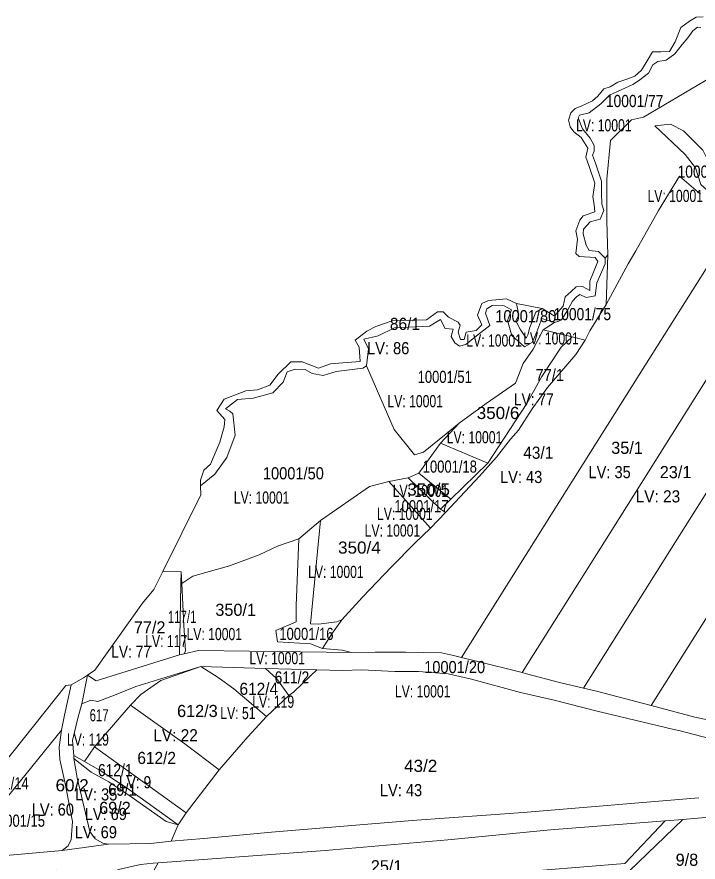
# Model space of a CAD drawing. Extents: x -713758 to -711119, y -1123067 to -1120789.
# Drawn here: x -712790 to -712228, y -1121659 to -1120963 of the extents above; entities that cross this region are included whole.
import ezdxf
from ezdxf.enums import TextEntityAlignment as Align

# ---------------------------------------------------------------- set-up
doc = ezdxf.new("R2010")
doc.units = 0
doc.header["$LTSCALE"] = 4
doc.layers.add('10', color=7, linetype='Continuous', lineweight=13)
doc.layers.add('11', color=7, linetype='Continuous')
doc.layers.add('13', color=7, linetype='Continuous')

msp = doc.modelspace()

# ---------------------------------------------------------------- linework, layer by layer
at = {"layer": '10'}
for points in [[(-712224.42, -1120963.08), (-712229.97, -1120963.16), (-712235.67, -1120966.55), (-712242.84, -1120971.92), (-712247.51, -1120983.72), (-712252.15, -1120991.62), (-712259.23, -1120991.94), (-712265.98, -1120991.96), (-712269.53, -1120998.02), (-712275.11, -1121006.86), (-712280.51, -1121011.9), (-712287.26, -1121014.28), (-712294.69, -1121016.71), (-712301.06, -1121020.69), (-712306.12, -1121022.38), (-712311.08, -1121028.3), (-712315.59, -1121032.08), (-712324.92, -1121036.66), (-712329.84, -1121038.62), (-712333.26, -1121042), (-712335.14, -1121048.22), (-712333.91, -1121053.74), (-712330.79, -1121057.62), (-712324.87, -1121062.34), (-712319.39, -1121071.27), (-712320.86, -1121078.69), (-712318.44, -1121085.37), (-712313.44, -1121100.01), (-712315.07, -1121111.24), (-712314.22, -1121117.5), (-712313.51, -1121123.67), (-712323.15, -1121126.92), (-712326.04, -1121130.58), (-712329.29, -1121139.33), (-712327.88, -1121146.11), (-712329.21, -1121158.1), (-712326.58, -1121160.43), (-712313.32, -1121161.17), (-712311.05, -1121164.48), (-712317.66, -1121180.78), (-712317.8, -1121188.36), (-712323.7, -1121185.03), (-712328.84, -1121185.35), (-712333.17, -1121189.3), (-712338.01, -1121193.72), (-712339.74, -1121201.43), (-712345.99, -1121208.39), (-712347.16, -1121209.3), (-712356.85, -1121203.31), (-712362.25, -1121206.21), (-712367.35, -1121219.37), (-712368.35, -1121224.5), (-712370.05, -1121227.81), (-712374.93, -1121220.33), (-712378.6, -1121213.35), (-712376.17, -1121208.67), (-712377.96, -1121199.21), (-712386.36, -1121195.27), (-712401.25, -1121196.63), (-712406.58, -1121199.11), (-712410.2, -1121208.83), (-712406.61, -1121216.8), (-712411.25, -1121221.32), (-712419.44, -1121222.82), (-712421.3, -1121228.7), (-712424.22, -1121228.79), (-712426.03, -1121222.66), (-712424.52, -1121217.12), (-712426.11, -1121214.63), (-712433.99, -1121210.38), (-712438.39, -1121206.13), (-712443.23, -1121206), (-712452.25, -1121212.71), (-712480.57, -1121213.53), (-712493.91, -1121218.11), (-712501.44, -1121222), (-712510.87, -1121229.48), (-712507.74, -1121235.25), (-712506.94, -1121246.96), (-712521.16, -1121247.99), (-712531.15, -1121248.85), (-712541.21, -1121252.33), (-712554.73, -1121247.31), (-712563.93, -1121247.29), (-712574.37, -1121257.45), (-712581.16, -1121266.47), (-712591.37, -1121270.33), (-712601.07, -1121271.03), (-712618.97, -1121277.89), (-712624.92, -1121287.25), (-712618.24, -1121294.85), (-712618.97, -1121300.73), (-712622.46, -1121313.42), (-712630.21, -1121331.54), (-712635.65, -1121336.52), (-712638.35, -1121344.65)], [(-712638.35, -1121344.65), (-712638.25, -1121349.38), (-712626.66, -1121339.88), (-712616.75, -1121326.09), (-712609.88, -1121307.54), (-712611.65, -1121290.13), (-712614.07, -1121287.84), (-712617.67, -1121285.95), (-712608.01, -1121278.11), (-712595.1, -1121277.06), (-712578.88, -1121272.62), (-712570.35, -1121263.93), (-712566.99, -1121255.5), (-712560.35, -1121253.18), (-712552.18, -1121253.58), (-712546.45, -1121256.89), (-712537.32, -1121258.45), (-712526.61, -1121255.29), (-712504.52, -1121252.44), (-712501.54, -1121250.48), (-712499.95, -1121236.38), (-712503.89, -1121228.47), (-712492.06, -1121225.81), (-712478.69, -1121219.22), (-712449.86, -1121217.79), (-712440.6, -1121212.38), (-712436.8, -1121219.7), (-712430.19, -1121220.2), (-712431.89, -1121226.25), (-712428.83, -1121231.53), (-712425.14, -1121234.31), (-712419.72, -1121232.98), (-712411.12, -1121225.79), (-712400.13, -1121217.31), (-712403.66, -1121207.21), (-712402.46, -1121203.44), (-712398.09, -1121200.87), (-712388.2, -1121200.98), (-712382.24, -1121204.31), (-712385.36, -1121213.25), (-712383.29, -1121220.86), (-712381.98, -1121225.65), (-712371.56, -1121234.82), (-712365.19, -1121231.4), (-712361.26, -1121222.53), (-712357.3, -1121211.49), (-712346.86, -1121214.84), (-712343.33, -1121213.8), (-712341.01, -1121212.69), (-712335.87, -1121204.25), (-712332.04, -1121197.29), (-712328.59, -1121193.6), (-712325.78, -1121191.79), (-712320.65, -1121194.25), (-712313.38, -1121192.75), (-712312, -1121182.24), (-712305.08, -1121166.47), (-712304.91, -1121161.72), (-712310.51, -1121156.25), (-712318.21, -1121155.46), (-712320.69, -1121151.04), (-712323.08, -1121141.82), (-712322.96, -1121137.97), (-712317.36, -1121131.81), (-712309.25, -1121129.8), (-712306.17, -1121122.47), (-712307.76, -1121117.45), (-712308.2, -1121108.1), (-712307.98, -1121098.34), (-712313.12, -1121083.51), (-712315.41, -1121077.09), (-712314, -1121073.54), (-712314.06, -1121069.02), (-712317.38, -1121063.06), (-712323.6, -1121055.16), (-712327.17, -1121046.2), (-712326.21, -1121044.06), (-712318.11, -1121042.2), (-712308.59, -1121034.55), (-712301.53, -1121027.44), (-712282.23, -1121018.77), (-712277.62, -1121015.73), (-712269.32, -1121009.56), (-712265.82, -1121002.65), (-712261.78, -1120999.7), (-712254.92, -1120998.58), (-712247.54, -1120993.58), (-712241.71, -1120985.84), (-712236.9, -1120980.4), (-712232.78, -1120974.54), (-712229.02, -1120971.51), (-712226.11, -1120971.88)], [(-712226.11, -1120971.88), (-712229.02, -1120971.51), (-712232.78, -1120974.54), (-712236.9, -1120980.4), (-712241.71, -1120985.84), (-712247.54, -1120993.58), (-712254.92, -1120998.58), (-712261.78, -1120999.7), (-712265.82, -1121002.65), (-712269.32, -1121009.56), (-712277.62, -1121015.73), (-712282.23, -1121018.77), (-712301.53, -1121027.44), (-712308.59, -1121034.55), (-712318.11, -1121042.2), (-712326.21, -1121044.06), (-712327.17, -1121046.2), (-712323.6, -1121055.16), (-712317.38, -1121063.06), (-712314.06, -1121069.02), (-712314, -1121073.54), (-712315.41, -1121077.09), (-712313.12, -1121083.51), (-712307.98, -1121098.34), (-712308.2, -1121108.1), (-712307.76, -1121117.45), (-712306.17, -1121122.47), (-712309.25, -1121129.8), (-712317.36, -1121131.81), (-712322.96, -1121137.97), (-712323.08, -1121141.82), (-712320.69, -1121151.04), (-712318.21, -1121155.46), (-712310.51, -1121156.25), (-712304.91, -1121161.72), (-712302.77, -1121158.96), (-712303.66, -1121131.47), (-712303.73, -1121096.86), (-712300.52, -1121064.83), (-712283.37, -1121047.99), (-712273.5, -1121045.77), (-712206.41, -1121006.04)], [(-712206.41, -1121006.04), (-712273.5, -1121045.77), (-712283.37, -1121047.99), (-712300.52, -1121064.83), (-712303.73, -1121096.86), (-712303.66, -1121131.47), (-712302.77, -1121158.96), (-712304.25, -1121199.91), (-712286.23, -1121166.59), (-712279.75, -1121155.73), (-712261.06, -1121122.55), (-712243.93, -1121094.31), (-712226.54, -1121109.19)], [(-712226.54, -1121109.19), (-712243.93, -1121094.31), (-712261.06, -1121122.55), (-712279.75, -1121155.73), (-712286.23, -1121166.59), (-712304.25, -1121199.91), (-712317.68, -1121221.61), (-712321.65, -1121229.23), (-712329.15, -1121241.06), (-712352.43, -1121268.46), (-712365.29, -1121286.03), (-712376.38, -1121303.44), (-712383, -1121310.86), (-712394.56, -1121325.76), (-712408.42, -1121341.27), (-712436.67, -1121371.26), (-712448.79, -1121384.35), (-712461.76, -1121396.57), (-712480.93, -1121416.03), (-712504.85, -1121441.12), (-712521.96, -1121459.65), (-712530.11, -1121471.27), (-712537.77, -1121483.27), (-712521.76, -1121484.83), (-712514.05, -1121486.77), (-712494.46, -1121486.25), (-712469.39, -1121486.31), (-712439.94, -1121487.05), (-712430.1, -1121488.99), (-712423.44, -1121490.64), (-712347.85, -1121370.61), (-712272.26, -1121250.57), (-712196.67, -1121130.54)], [(-712221.92, -1121541.87), (-712231.21, -1121539.78), (-712267.18, -1121530.34), (-712312.23, -1121518.51), (-712322.84, -1121515.97), (-712342.53, -1121511.25), (-712369.84, -1121504.13), (-712373.44, -1121503.22), (-712411.12, -1121493.7), (-712423.44, -1121490.64), (-712430.1, -1121488.99), (-712439.94, -1121487.05), (-712469.39, -1121486.31), (-712494.46, -1121486.25), (-712514.05, -1121486.77), (-712639.91, -1121484.94), (-712651.92, -1121487.77), (-712655.74, -1121488.57), (-712724.24, -1121509.87), (-712731.39, -1121505.21), (-712736.15, -1121529.01), (-712728.69, -1121525.95), (-712722.98, -1121527.12), (-712709.28, -1121521.78), (-712691.5, -1121514.66), (-712638.03, -1121498.16), (-712584.9, -1121499.71), (-712542.46, -1121500.8), (-712521.21, -1121501.35), (-712505.59, -1121500.85), (-712478.34, -1121502.43), (-712458.67, -1121502.22), (-712434.5, -1121504.3), (-712415.23, -1121508.73), (-712374.86, -1121519.68), (-712347.09, -1121525.83), (-712311.55, -1121535.01), (-712249.63, -1121549.72), (-712243.26, -1121551.08), (-712212.92, -1121559.2)], [(-712212.92, -1121559.2), (-712243.26, -1121551.08), (-712249.63, -1121549.72), (-712311.55, -1121535.01), (-712347.09, -1121525.83), (-712374.86, -1121519.68), (-712415.23, -1121508.73), (-712434.5, -1121504.3), (-712458.67, -1121502.22), (-712478.34, -1121502.43), (-712505.59, -1121500.85), (-712521.21, -1121501.35), (-712542.46, -1121500.8), (-712547.82, -1121505.92), (-712561.9, -1121519.34), (-712565.66, -1121522.02), (-712584.01, -1121539.3), (-712599.25, -1121556.05), (-712623, -1121583.43), (-712650.07, -1121618.72), (-712656.83, -1121628.57), (-712662.45, -1121642.03), (-712635.72, -1121639.83), (-712580.02, -1121634.77), (-712464.09, -1121624.94), (-712372.57, -1121618.47), (-712228.02, -1121606.32)], [(-712829.35, -1121656.74), (-712752.3, -1121649.86), (-712714.25, -1121644.62), (-712679.19, -1121643.9), (-712662.45, -1121642.03), (-712635.72, -1121639.83), (-712580.02, -1121634.77), (-712464.09, -1121624.94), (-712372.57, -1121618.47), (-712228.02, -1121606.32)], [(-712201.33, -1121620.73), (-712241.17, -1121624.1), (-712255.74, -1121625.24), (-712350.1, -1121632.59), (-712434.68, -1121640.83), (-712535.55, -1121649.68), (-712673.12, -1121659.8), (-712677.41, -1121660.12), (-712687.79, -1121661.3), (-712705.83, -1121665.37), (-712711.27, -1121667.93), (-712716.34, -1121673.15), (-712734.88, -1121675.75), (-712740.68, -1121669.42), (-712748.52, -1121666.41), (-712756.64, -1121665.93), (-712811.56, -1121670.57)], [(-712284.89, -1121666.46), (-712241.17, -1121624.1), (-712255.74, -1121625.24), (-712288.77, -1121660.36)]]:
    msp.add_lwpolyline(points, dxfattribs=at)
for points in [[(-712264.11, -1121052.71), (-712239.09, -1121076.45), (-712230.76, -1121087.53), (-712226.25, -1121101.15), (-712200.43, -1121124.56), (-712186.09, -1121132.32), (-712178.22, -1121136.29), (-712166.82, -1121136.13), (-712166.03, -1121127.39), (-712177.11, -1121119.56), (-712186.97, -1121112.79), (-712203.92, -1121102.45), (-712218.34, -1121085.52), (-712224.47, -1121072.79), (-712240.53, -1121057.06), (-712251.27, -1121051.42)], [(-712264.11, -1121052.71), (-712251.27, -1121051.42), (-712240.53, -1121057.06), (-712224.47, -1121072.79), (-712218.34, -1121085.52), (-712203.92, -1121102.45), (-712186.97, -1121112.79), (-712177.11, -1121119.56), (-712166.03, -1121127.39), (-712166.82, -1121136.13), (-712178.22, -1121136.29), (-712186.09, -1121132.32), (-712200.43, -1121124.56), (-712226.25, -1121101.15), (-712230.76, -1121087.53), (-712239.09, -1121076.45)], [(-712423.44, -1121490.64), (-712347.85, -1121370.61), (-712272.26, -1121250.57), (-712196.67, -1121130.54), (-712185, -1121136.71), (-712169.32, -1121143.39), (-712151.71, -1121151.12), (-712225.62, -1121268.49), (-712299.53, -1121385.85), (-712373.44, -1121503.22), (-712411.12, -1121493.7)], [(-712373.44, -1121503.22), (-712299.53, -1121385.85), (-712225.62, -1121268.49), (-712151.71, -1121151.12), (-712121.32, -1121164.46), (-712105.15, -1121170.27), (-712177.71, -1121285.5), (-712250.27, -1121400.74), (-712322.84, -1121515.97), (-712342.53, -1121511.25), (-712369.84, -1121504.13)], [(-712356.08, -1121220.95), (-712332.16, -1121226.7), (-712321.65, -1121229.23), (-712317.68, -1121221.61), (-712304.25, -1121199.91), (-712302.77, -1121158.96), (-712304.91, -1121161.72), (-712305.08, -1121166.47), (-712312, -1121182.24), (-712313.38, -1121192.75), (-712320.65, -1121194.25), (-712325.78, -1121191.79), (-712328.59, -1121193.6), (-712332.04, -1121197.29), (-712335.87, -1121204.25), (-712341.01, -1121212.69), (-712343.33, -1121213.8), (-712346.86, -1121214.84)], [(-712322.84, -1121515.97), (-712250.27, -1121400.74), (-712177.71, -1121285.5), (-712105.15, -1121170.27), (-712076.52, -1121180.56), (-712064.5, -1121183.42), (-712050.6, -1121186.42), (-712122.79, -1121301.06), (-712194.99, -1121415.7), (-712267.18, -1121530.34), (-712312.23, -1121518.51)], [(-712267.18, -1121530.34), (-712194.99, -1121415.7), (-712122.79, -1121301.06), (-712050.6, -1121186.42), (-712045.54, -1121187.51), (-712026.93, -1121189.41), (-712000.06, -1121191.51), (-712073.66, -1121308.39), (-712147.26, -1121425.26), (-712220.86, -1121542.14), (-712221.92, -1121541.87), (-712231.21, -1121539.78)], [(-712503.89, -1121228.47), (-712499.95, -1121236.38), (-712501.54, -1121250.48), (-712478.94, -1121303.07), (-712462.23, -1121323.77), (-712454.65, -1121321.49), (-712436.07, -1121306.41), (-712425.21, -1121297.67), (-712403.14, -1121281.61), (-712378.77, -1121264.75), (-712372.68, -1121248.63), (-712364.35, -1121236.66), (-712356.08, -1121220.95), (-712346.86, -1121214.84), (-712357.3, -1121211.49), (-712361.26, -1121222.53), (-712365.19, -1121231.4), (-712371.56, -1121234.82), (-712381.98, -1121225.65), (-712383.29, -1121220.86), (-712385.36, -1121213.25), (-712382.24, -1121204.31), (-712388.2, -1121200.98), (-712398.09, -1121200.87), (-712402.46, -1121203.44), (-712403.66, -1121207.21), (-712400.13, -1121217.31), (-712411.12, -1121225.79), (-712419.72, -1121232.98), (-712425.14, -1121234.31), (-712428.83, -1121231.53), (-712431.89, -1121226.25), (-712430.19, -1121220.2), (-712436.8, -1121219.7), (-712440.6, -1121212.38), (-712449.86, -1121217.79), (-712478.69, -1121219.22), (-712492.06, -1121225.81)], [(-712378.6, -1121213.35), (-712374.93, -1121220.33), (-712370.05, -1121227.81), (-712368.35, -1121224.5), (-712367.35, -1121219.37), (-712362.25, -1121206.21), (-712356.85, -1121203.31), (-712377.96, -1121199.21), (-712376.17, -1121208.67)], [(-712440.65, -1121314.3), (-712401.72, -1121330.62), (-712369.68, -1121281.6), (-712357.24, -1121259.22), (-712341.2, -1121235.2), (-712332.16, -1121226.7), (-712356.08, -1121220.95), (-712364.35, -1121236.66), (-712372.68, -1121248.63), (-712378.77, -1121264.75), (-712403.14, -1121281.61), (-712425.21, -1121297.67)], [(-712440.61, -1121368.69), (-712436.67, -1121371.26), (-712408.42, -1121341.27), (-712394.56, -1121325.76), (-712383, -1121310.86), (-712376.38, -1121303.44), (-712365.29, -1121286.03), (-712352.43, -1121268.46), (-712329.15, -1121241.06), (-712321.65, -1121229.23), (-712332.16, -1121226.7), (-712341.2, -1121235.2), (-712357.24, -1121259.22), (-712369.68, -1121281.6), (-712401.72, -1121330.62), (-712432.15, -1121360.41)], [(-712669.26, -1121419.84), (-712654.24, -1121420.15), (-712653.78, -1121429.78), (-712644.81, -1121423.71), (-712614.56, -1121415.28), (-712589.95, -1121406.22), (-712575.05, -1121398.94), (-712557.36, -1121393), (-712539.39, -1121377.79), (-712499.03, -1121349.77), (-712483.18, -1121345.84), (-712467.38, -1121342.75), (-712458.58, -1121338.81), (-712440.65, -1121314.3), (-712425.21, -1121297.67), (-712436.07, -1121306.41), (-712454.65, -1121321.49), (-712462.23, -1121323.77), (-712478.94, -1121303.07), (-712501.54, -1121250.48), (-712504.52, -1121252.44), (-712526.61, -1121255.29), (-712537.32, -1121258.45), (-712546.45, -1121256.89), (-712552.18, -1121253.58), (-712560.35, -1121253.18), (-712566.99, -1121255.5), (-712570.35, -1121263.93), (-712578.88, -1121272.62), (-712595.1, -1121277.06), (-712608.01, -1121278.11), (-712617.67, -1121285.95), (-712614.07, -1121287.84), (-712611.65, -1121290.13), (-712609.88, -1121307.54), (-712616.75, -1121326.09), (-712626.66, -1121339.88), (-712638.25, -1121349.38), (-712638.1, -1121356.72)], [(-712458.58, -1121338.81), (-712432.15, -1121360.41), (-712401.72, -1121330.62), (-712440.65, -1121314.3)], [(-712483.18, -1121345.84), (-712448.79, -1121384.35), (-712436.67, -1121371.26), (-712440.61, -1121368.69), (-712467.38, -1121342.75)], [(-712467.38, -1121342.75), (-712440.61, -1121368.69), (-712432.15, -1121360.41), (-712458.58, -1121338.81)], [(-712547.79, -1121463.01), (-712541.23, -1121463.22), (-712526.04, -1121461.35), (-712521.96, -1121459.65), (-712504.85, -1121441.12), (-712480.93, -1121416.03), (-712461.76, -1121396.57), (-712448.79, -1121384.35), (-712483.18, -1121345.84), (-712499.03, -1121349.77), (-712539.39, -1121377.79)], [(-712576.37, -1121468.4), (-712575.02, -1121477.85), (-712547.66, -1121479.54), (-712537.77, -1121483.27), (-712530.11, -1121471.27), (-712521.96, -1121459.65), (-712526.04, -1121461.35), (-712541.23, -1121463.22), (-712547.79, -1121463.01), (-712539.39, -1121377.79), (-712557.36, -1121393), (-712559.64, -1121447.91), (-712559.68, -1121461.33)], [(-712653.78, -1121429.78), (-712652.12, -1121464.34), (-712650.65, -1121485.2), (-712651.92, -1121487.77), (-712639.91, -1121484.94), (-712514.05, -1121486.77), (-712521.76, -1121484.83), (-712537.77, -1121483.27), (-712547.66, -1121479.54), (-712575.02, -1121477.85), (-712576.37, -1121468.4), (-712559.68, -1121461.33), (-712559.64, -1121447.91), (-712557.36, -1121393), (-712575.05, -1121398.94), (-712589.95, -1121406.22), (-712614.56, -1121415.28), (-712644.81, -1121423.71)], [(-712731.39, -1121505.21), (-712724.24, -1121509.87), (-712655.74, -1121488.57), (-712654.48, -1121430.25), (-712654.24, -1121420.15), (-712669.26, -1121419.84), (-712676.89, -1121434.62), (-712686.18, -1121445.9), (-712725.31, -1121501.17)], [(-712655.74, -1121488.57), (-712654.48, -1121430.25), (-712654.24, -1121420.15), (-712653.78, -1121429.78), (-712652.12, -1121464.34), (-712650.65, -1121485.2), (-712651.92, -1121487.77)], [(-712743.86, -1121559.24), (-712742.8, -1121571.5), (-712734.01, -1121576.43), (-712725.74, -1121564.24), (-712696.07, -1121529.89), (-712687.53, -1121521.3), (-712671.17, -1121509.65), (-712638.03, -1121498.16), (-712691.5, -1121514.66), (-712709.28, -1121521.78), (-712722.98, -1121527.12), (-712728.69, -1121525.95), (-712736.15, -1121529.01), (-712739.03, -1121539.72)], [(-712696.07, -1121529.89), (-712651.29, -1121561.99), (-712623, -1121583.43), (-712599.25, -1121556.05), (-712584.01, -1121539.3), (-712610.8, -1121516.6), (-712623.7, -1121507.1), (-712638.03, -1121498.16), (-712671.17, -1121509.65), (-712687.53, -1121521.3)], [(-712638.03, -1121498.16), (-712623.7, -1121507.1), (-712610.8, -1121516.6), (-712584.01, -1121539.3), (-712565.66, -1121522.02), (-712575.68, -1121507.96), (-712584.9, -1121499.71)], [(-712584.9, -1121499.71), (-712542.46, -1121500.8), (-712547.82, -1121505.92), (-712561.9, -1121519.34), (-712565.66, -1121522.02), (-712575.68, -1121507.96)], [(-712754.67, -1121564.53), (-712754.14, -1121574.84), (-712749.88, -1121594.58), (-712743.67, -1121625.84), (-712745.02, -1121640.69), (-712747.43, -1121645.94), (-712752.3, -1121649.86), (-712714.25, -1121644.62), (-712718.91, -1121643.72), (-712725.1, -1121640.01), (-712729.48, -1121634.07), (-712739.94, -1121589.8), (-712742.6, -1121573.83), (-712742.8, -1121571.5), (-712743.86, -1121559.24), (-712739.03, -1121539.72), (-712736.15, -1121529.01), (-712731.39, -1121505.21), (-712734.73, -1121507.43), (-712744.77, -1121513.2), (-712750.3, -1121538.21), (-712752.88, -1121550.69)], [(-712888.87, -1121658.79), (-712885.65, -1121658.68), (-712864.22, -1121657.94), (-712845.67, -1121640.48), (-712817.6, -1121624.66), (-712795.86, -1121603.97), (-712752.88, -1121550.69), (-712750.3, -1121538.21), (-712744.77, -1121513.2), (-712749.34, -1121513.8), (-712811.48, -1121591.48), (-712818.41, -1121597.09), (-712831.79, -1121610.57), (-712848.31, -1121615.15), (-712856.5, -1121624.23), (-712868.15, -1121630.5), (-712882.05, -1121646.55)], [(-712725.74, -1121564.24), (-712650.07, -1121618.72), (-712623, -1121583.43), (-712651.29, -1121561.99), (-712696.07, -1121529.89)], [(-712864.22, -1121657.94), (-712829.35, -1121656.74), (-712752.3, -1121649.86), (-712747.43, -1121645.94), (-712745.02, -1121640.69), (-712743.67, -1121625.84), (-712749.88, -1121594.58), (-712754.14, -1121574.84), (-712754.67, -1121564.53), (-712752.88, -1121550.69), (-712795.86, -1121603.97), (-712817.6, -1121624.66), (-712845.67, -1121640.48)], [(-712734.01, -1121576.43), (-712721.13, -1121583.73), (-712698.68, -1121598.5), (-712656.83, -1121628.57), (-712650.07, -1121618.72), (-712725.74, -1121564.24)], [(-712742.8, -1121571.5), (-712742.6, -1121573.83), (-712728.48, -1121585.2), (-712713.98, -1121593.15), (-712695.58, -1121605.66), (-712666.53, -1121625.95), (-712656.83, -1121628.57), (-712698.68, -1121598.5), (-712721.13, -1121583.73), (-712734.01, -1121576.43)], [(-712742.6, -1121573.83), (-712739.94, -1121589.8), (-712729.48, -1121634.07), (-712725.1, -1121640.01), (-712718.91, -1121643.72), (-712714.25, -1121644.62), (-712679.19, -1121643.9), (-712662.45, -1121642.03), (-712656.83, -1121628.57), (-712666.53, -1121625.95), (-712695.58, -1121605.66), (-712713.98, -1121593.15), (-712728.48, -1121585.2)], [(-712310.25, -1121694.64), (-712229.88, -1121697.85), (-712138.38, -1121614.8), (-712201.33, -1121620.73), (-712241.17, -1121624.1), (-712284.89, -1121666.46)], [(-712693.92, -1121693.86), (-712685.27, -1121681.19), (-712673.12, -1121659.8), (-712535.55, -1121649.68), (-712434.68, -1121640.83), (-712350.1, -1121632.59), (-712255.74, -1121625.24), (-712288.77, -1121660.36), (-712423.82, -1121671.53), (-712558.87, -1121682.69)]]:
    msp.add_lwpolyline(points, close=True, dxfattribs=at)

# ---------------------------------------------------------------- texts
at = {"layer": '11'}
for s, width, p in [('10001/77', 0.85, (-712280.73, -1121037.36)), ('10001/76', 0.85, (-712221.69, -1121095.54)), ('10001/80', 0.9, (-712370.441, -1121214.61)), ('10001/75', 0.85, (-712323.851, -1121212.9)), ('86/1', 0.95, (-712469.99, -1121220.96)), ('10001/51', 0.8, (-712437.2, -1121264.6)), ('77/1', 0.9, (-712350.67, -1121263.12)), ('350/6', 1.05, (-712393.299, -1121294.33)), ('43/1', 0.95, (-712360.15, -1121327.06)), ('10001/18', 0.8, (-712433, -1121338.51)), ('10001/50', 0.9, (-712561.87, -1121344.02)), ('350/5', 1.05, (-712450.5, -1121357.39)), ('10001/17', 0.8, (-712456.38, -1121371.15)), ('350/4', 1.05, (-712507.48, -1121405.22)), ('117/1', 0.7, (-712653.46, -1121462.24)), ('10001/16', 0.8, (-712551.111, -1121476.28)), ('10001/20', 0.9, (-712429.03, -1121503.64)), ('611/2', 0.85, (-712563.061, -1121512.16)), ('612/4', 0.95, (-712590.351, -1121521.54)), ('617', 0.7, (-712721.89, -1121543.33)), ('612/2', 0.95, (-712674.481, -1121578.51)), ('43/2', 1.05, (-712456.99, -1121585.02)), ('612/1', 0.85, (-712708.561, -1121588.52)), ('10001/14', 0.8, (-712802.16, -1121599.44)), ('60/2', 1.05, (-712744.1, -1121601)), ('69/1', 0.9, (-712702.73, -1121604.64)), ('10001/15', 0.8, (-712788.78, -1121630.19))]:
    msp.add_text(s, height=10, dxfattribs=dict(at, width=width)).set_placement(p, align=Align.CENTER)
for s, p in [('35/1', (-712287.049, -1121323.04)), ('23/1', (-712247.059, -1121343.03)), ('350/1', (-712609.4, -1121456.45)), ('77/2', (-712680.25, -1121470.95)), ('612/3', (-712640.929, -1121539.8)), ('69/2', (-712708.83, -1121619.63)), ('25/1', (-712485.061, -1121667.71)), ('9/8', (-712237.69, -1121662.36))]:
    msp.add_text(s, height=10, dxfattribs=at).set_placement(p, align=Align.CENTER)
at = {"layer": '13'}
for s, width, p in [('LV: 10001 ', 0.75, (-712304.754, -1121057.36)), ('LV: 10001 ', 0.75, (-712245.915, -1121115.54)), ('LV: 10001 ', 0.75, (-712395.134, -1121234.61)), ('LV: 10001 ', 0.75, (-712348.31, -1121232.9)), ('LV: 86 ', 0.9, (-712482.101, -1121240.96)), ('LV: 10001 ', 0.75, (-712460.12, -1121284.6)), ('LV: 77 ', 0.85, (-712362.247, -1121283.12)), ('LV: 10001 ', 0.75, (-712411.268, -1121314.33)), ('LV: 43 ', 0.9, (-712372.564, -1121347.06)), ('LV: 35 ', 0.9, (-712299.698, -1121343.04)), ('LV: 10001 ', 0.75, (-712455.786, -1121358.51)), ('LV: 10001 ', 0.75, (-712586.664, -1121364.02)), ('LV: 23 ', 0.95, (-712259.841, -1121363.03)), ('LV: 10001 ', 0.75, (-712468.703, -1121377.39)), ('LV: 10001 ', 0.75, (-712478.865, -1121391.15)), ('LV: 10001 ', 0.75, (-712525.448, -1121425.22)), ('LV: 10001 ', 0.75, (-712625.628, -1121476.45)), ('LV: 117 ', 0.75, (-712665.204, -1121482.24)), ('LV: 77 ', 0.85, (-712693.936, -1121490.95)), ('LV: 10001 ', 0.75, (-712573.796, -1121496.28)), ('LV: 10001 ', 0.75, (-712453.958, -1121523.64)), ('LV: 119 ', 0.75, (-712577.113, -1121532.16)), ('LV: 51 ', 0.75, (-712606.144, -1121541.54)), ('LV: 119 ', 0.75, (-712729.72, -1121563.33)), ('LV: 22 ', 0.95, (-712657.157, -1121559.8)), ('LV: 9 ', 0.85, (-712690.642, -1121598.51)), ('LV: 43 ', 0.9, (-712471.512, -1121605.02)), ('LV: 35 ', 0.9, (-712722.613, -1121608.52)), ('LV: 60 ', 0.9, (-712758.321, -1121621)), ('LV: 69 ', 0.9, (-712714.708, -1121624.64)), ('LV: 69 ', 0.9, (-712722.917, -1121639.63))]:
    msp.add_text(s, height=10, dxfattribs=dict(at, width=width)).set_placement(p, align=Align.CENTER)

doc.saveas('drawing.dxf')
